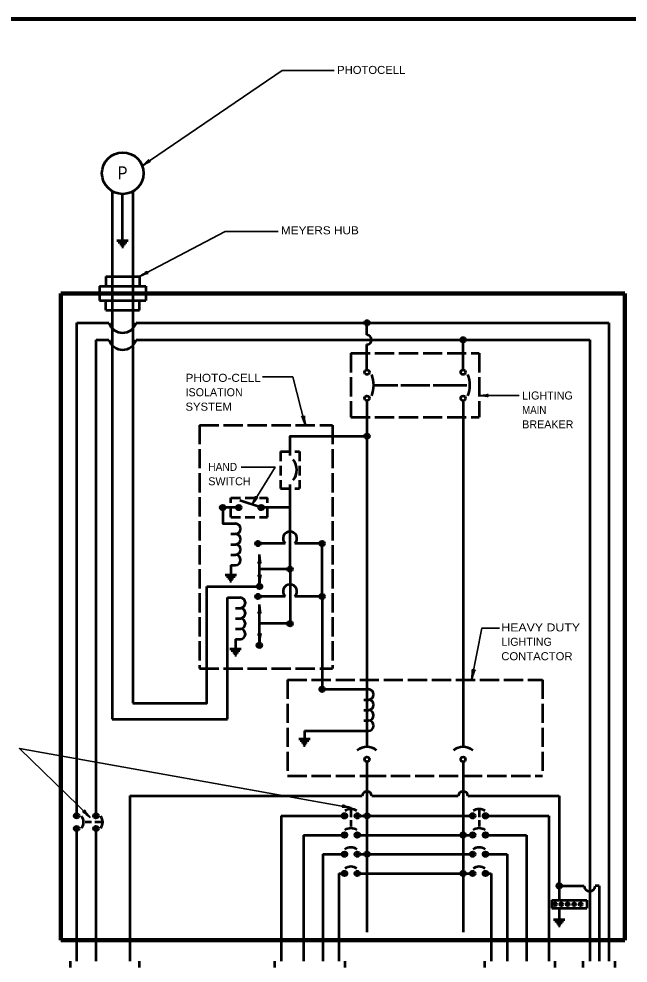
# Model space of a CAD drawing. Extents: x -35 to 821, y -18 to 526.
# Drawn here: x 359.2 to 587.3, y 165.4 to 519.2 of the extents above; entities that cross this region are included whole.
import ezdxf

# ---------------------------------------------------------------- set-up
doc = ezdxf.new("R2010")
doc.units = 0
doc.header["$LTSCALE"] = 1.2
doc.linetypes.add('LONG_DASHED', pattern=[7.5, 6, -1.5])
doc.linetypes.add('MEDIUM_DASHED', pattern=[4.5, 3, -1.5])
doc.layers.add('1', color=7, linetype='Continuous', lineweight=53)

msp = doc.modelspace()

# ---------------------------------------------------------------- hatches: boundary and pattern name
at = {"layer": '1'}
for points in [[(490.425, 405.327, 1), (488.625, 405.327, 1)], [(526.425, 398.986, 1), (524.625, 398.986, 1)], [(490.425, 362.807, 1), (488.625, 362.807, 1)], [(436.425, 336.107, 1), (434.625, 336.107, 1)], [(442.425, 336.107, 1), (440.625, 336.107, 1)], [(450.825, 336.107, 1), (449.025, 336.107, 1)], [(449.625, 322.607, 1), (447.825, 322.607, 1)], [(473.625, 322.607, 1), (471.825, 322.607, 1)], [(461.625, 313.007, 1), (459.825, 313.007, 1)], [(450.225, 306.557, 1), (448.425, 306.557, 1)], [(449.625, 302.807, 1), (447.825, 302.807, 1)], [(473.625, 302.807, 1), (471.825, 302.807, 1)], [(461.625, 292.607, 1), (459.825, 292.607, 1)], [(450.142, 284.482, 1), (448.342, 284.482, 1)], [(473.625, 268.007, 1), (471.825, 268.007, 1)], [(380.848, 219.726, 1), (380.848, 221.526, 1)], [(388.048, 219.726, 1), (388.048, 221.526, 1)], [(482.025, 220.607, 1), (480.225, 220.607, 1)], [(486.825, 220.607, 1), (485.025, 220.607, 1)], [(490.425, 220.607, 1), (488.625, 220.607, 1)], [(530.025, 220.607, 1), (528.225, 220.607, 1)], [(534.825, 220.607, 1), (533.025, 220.607, 1)], [(380.848, 214.926, 1), (380.848, 216.726, 1)], [(388.048, 214.926, 1), (388.048, 216.726, 1)], [(482.025, 213.407, 1), (480.225, 213.407, 1)], [(486.825, 213.407, 1), (485.025, 213.407, 1)], [(526.425, 213.407, 1), (524.625, 213.407, 1)], [(530.025, 213.407, 1), (528.225, 213.407, 1)], [(534.825, 213.407, 1), (533.025, 213.407, 1)], [(482.025, 206.207, 1), (480.225, 206.207, 1)], [(486.825, 206.207, 1), (485.025, 206.207, 1)], [(490.425, 206.207, 1), (488.625, 206.207, 1)], [(530.025, 206.207, 1), (528.225, 206.207, 1)], [(534.825, 206.207, 1), (533.025, 206.207, 1)], [(482.025, 199.007, 1), (480.225, 199.007, 1)], [(486.825, 199.007, 1), (485.025, 199.007, 1)], [(526.425, 199.007, 1), (524.625, 199.007, 1)], [(530.025, 199.007, 1), (528.225, 199.007, 1)], [(534.825, 199.007, 1), (533.025, 199.007, 1)], [(562.425, 194.357, 1), (560.625, 194.357, 1)], [(560.516, 187.457, 1), (559.316, 187.457, 1)], [(562.916, 187.457, 1), (561.716, 187.457, 1)], [(565.316, 187.457, 1), (564.116, 187.457, 1)], [(567.716, 187.457, 1), (566.516, 187.457, 1)], [(570.116, 187.457, 1), (568.916, 187.457, 1)]]:
    msp.add_hatch(color=256, dxfattribs=at).paths.add_polyline_path(points)

# ---------------------------------------------------------------- linework, layer by layer
for p, q in [((394.125, 454.661), (394.125, 256.757)), ((398.025, 436.177), (398.025, 453.577)), ((401.925, 454.583), (401.925, 262.757)), ((395.925, 436.177), (400.125, 436.177)), ((396.375, 435.577), (399.675, 435.577)), ((396.975, 434.977), (399.075, 434.977)), ((397.425, 434.377), (398.625, 434.377)), ((397.725, 433.777), (398.325, 433.777)), ((391.725, 422.657), (404.325, 422.657)), ((391.725, 422.657), (391.725, 419.057)), ((404.325, 422.657), (404.325, 419.057)), ((389.325, 419.057), (406.725, 419.057)), ((389.325, 419.057), (389.325, 413.657)), ((406.725, 419.057), (406.725, 413.657)), ((389.325, 413.657), (406.725, 413.657)), ((391.725, 410.057), (391.725, 413.657)), ((404.325, 410.057), (404.325, 413.657)), ((391.725, 410.057), (404.325, 410.057)), ((380.925, 405.327), (392.925, 405.327)), ((380.925, 220.607), (380.925, 405.327)), ((403.125, 405.327), (580.125, 405.327)), ((489.525, 400.786), (489.525, 405.327)), ((580.125, 405.327), (580.125, 166.157)), ((388.125, 398.986), (392.925, 398.986)), ((388.125, 220.607), (388.125, 398.986)), ((403.125, 398.986), (572.925, 398.986)), ((489.525, 387.707), (489.525, 397.186)), ((525.525, 387.707), (525.525, 398.986)), ((572.925, 398.986), (572.925, 166.157)), ((492.071, 381.932), (501.071, 381.932)), ((502.271, 381.932), (513.071, 381.932)), ((514.271, 381.932), (526.871, 381.932)), ((489.525, 376.157), (489.525, 246.407)), ((525.525, 376.157), (525.525, 246.407)), ((460.725, 313.007), (460.725, 344.807)), ((449.925, 336.107), (441.936, 338.703)), ((441.525, 336.107), (435.525, 336.107)), ((460.725, 336.107), (449.925, 336.107)), ((438.525, 326.207), (440.325, 326.207)), ((438.525, 322.307), (440.325, 322.307)), ((458.925, 322.607), (448.725, 322.607)), ((449.325, 307.457), (449.325, 318.557)), ((438.525, 318.407), (440.325, 318.407)), ((438.525, 314.507), (440.325, 314.507)), ((438.525, 314.507), (438.525, 310.907)), ((460.725, 313.007), (449.325, 313.007)), ((436.425, 310.907), (440.625, 310.907)), ((436.875, 310.307), (440.175, 310.307)), ((437.475, 309.707), (439.575, 309.707)), ((437.925, 309.107), (439.125, 309.107)), ((438.225, 308.507), (438.825, 308.507)), ((429.525, 306.557), (449.325, 306.557)), ((437.325, 256.757), (437.325, 302.357)), ((437.325, 302.357), (442.125, 302.357)), ((458.925, 302.807), (448.725, 302.807)), ((472.725, 302.807), (462.525, 302.807)), ((440.325, 298.457), (442.125, 298.457)), ((449.325, 285.407), (449.325, 299.807)), ((440.325, 294.557), (442.125, 294.557)), ((440.325, 290.657), (442.125, 290.657)), ((440.325, 286.757), (442.125, 286.757)), ((440.325, 286.757), (440.325, 283.157)), ((438.225, 283.157), (442.425, 283.157)), ((438.675, 282.557), (441.975, 282.557)), ((439.275, 281.957), (441.375, 281.957)), ((439.725, 281.357), (440.925, 281.357)), ((440.025, 280.757), (440.625, 280.757)), ((489.525, 268.007), (490.125, 268.007)), ((488.325, 264.107), (490.125, 264.107)), ((488.325, 260.207), (490.125, 260.207)), ((394.125, 256.757), (437.325, 256.757)), ((488.325, 256.307), (490.125, 256.307)), ((466.125, 252.407), (490.125, 252.407)), ((466.125, 252.407), (466.125, 249.407)), ((464.025, 249.407), (468.225, 249.407)), ((464.475, 248.807), (467.775, 248.807)), ((465.075, 248.207), (467.175, 248.207)), ((465.525, 247.607), (466.725, 247.607)), ((465.825, 247.007), (466.425, 247.007)), ((489.525, 240.857), (489.525, 176.957)), ((525.525, 240.857), (525.525, 176.957)), ((400.725, 228.107), (400.725, 166.157)), ((400.725, 228.107), (487.725, 228.107)), ((491.325, 228.107), (523.725, 228.107)), ((527.325, 228.107), (561.525, 228.107)), ((561.525, 228.107), (561.525, 188.957)), ((388.125, 219.694), (388.125, 220.607)), ((457.425, 220.607), (457.425, 166.157)), ((457.425, 220.607), (481.125, 220.607)), ((483.525, 222.551), (483.525, 220.151)), ((485.925, 220.607), (529.125, 220.607)), ((531.525, 222.551), (531.525, 220.151)), ((533.925, 220.607), (557.625, 220.607)), ((557.625, 220.607), (557.625, 166.157)), ((386.391, 218.226), (383.991, 218.226)), ((389.991, 218.226), (387.591, 218.226)), ((388.125, 166.157), (388.125, 215.847)), ((483.525, 218.951), (483.525, 216.551)), ((531.525, 218.951), (531.525, 216.551)), ((380.925, 166.157), (380.925, 215.731)), ((465.825, 213.407), (481.125, 213.407)), ((465.825, 213.407), (465.825, 166.157)), ((485.925, 213.407), (529.125, 213.407)), ((533.925, 213.407), (549.225, 213.407)), ((549.225, 213.407), (549.225, 166.157)), ((473.025, 206.207), (481.125, 206.207)), ((473.025, 206.207), (473.025, 166.157)), ((485.925, 206.207), (529.125, 206.207)), ((533.925, 206.207), (542.025, 206.207)), ((542.025, 206.207), (542.025, 166.157)), ((479.025, 199.007), (481.125, 199.007)), ((479.025, 199.007), (479.025, 166.157)), ((485.925, 199.007), (529.125, 199.007)), ((533.925, 199.007), (536.025, 199.007)), ((536.025, 199.007), (536.025, 166.157)), ((561.525, 194.357), (570.825, 194.357)), ((576.525, 194.357), (575.025, 194.357)), ((576.525, 194.357), (576.525, 166.157)), ((558.716, 188.957), (571.916, 188.957)), ((558.716, 188.957), (558.716, 185.957)), ((571.916, 188.957), (571.916, 185.957)), ((558.716, 185.957), (571.916, 185.957)), ((561.525, 185.957), (561.525, 181.757)), ((559.425, 181.757), (563.625, 181.757)), ((559.875, 181.157), (563.175, 181.157)), ((560.475, 180.557), (562.575, 180.557)), ((560.925, 179.957), (562.125, 179.957)), ((561.225, 179.357), (561.825, 179.357)), ((378.525, 163.757), (378.525, 166.157)), ((404.325, 163.757), (404.325, 166.157)), ((455.025, 163.757), (455.025, 166.157)), ((481.425, 163.757), (481.425, 166.157)), ((533.625, 163.757), (533.625, 166.157)), ((560.025, 163.757), (560.025, 166.157)), ((570.525, 163.757), (570.525, 166.157)), ((582.525, 163.757), (582.525, 166.157))]:
    msp.add_line(p, q, dxfattribs=at)
at = {"layer": '1', "lineweight": 140}
for p, q in [((374.925, 416.357), (374.925, 173.957)), ((374.925, 416.357), (586.125, 416.357)), ((586.125, 416.357), (586.125, 173.957)), ((374.925, 173.957), (586.125, 173.957))]:
    msp.add_line(p, q, dxfattribs=at)
at = {"layer": '1', "linetype": 'LONG_DASHED'}
for p, q in [((483.525, 393.932), (531.525, 393.932)), ((483.525, 393.932), (483.525, 369.932)), ((531.525, 393.932), (531.525, 369.932)), ((483.525, 369.932), (531.525, 369.932)), ((426.825, 367.007), (476.625, 367.007)), ((426.825, 367.007), (426.825, 275.807)), ((476.625, 367.007), (476.625, 275.807)), ((426.825, 275.807), (476.625, 275.807)), ((459.825, 271.607), (555.225, 271.607)), ((459.825, 271.607), (459.825, 235.607)), ((555.225, 271.607), (555.225, 235.607))]:
    msp.add_line(p, q, dxfattribs=at)
at = {"layer": '1', "lineweight": 35}
msp.add_line((531.525, 378.087), (546.475, 378.087), dxfattribs=at)
at = {"layer": '1', "linetype": 'MEDIUM_DASHED'}
for p, q in [((457.125, 357.107), (464.325, 357.107)), ((457.125, 357.107), (457.125, 343.307)), ((464.325, 357.107), (464.325, 343.307)), ((457.125, 343.307), (464.325, 343.307)), ((438.525, 332.507), (438.525, 339.707)), ((438.525, 339.707), (452.325, 339.707)), ((452.325, 332.507), (452.325, 339.707)), ((438.525, 332.507), (452.325, 332.507))]:
    msp.add_line(p, q, dxfattribs=at)
at = {"layer": '1', "lineweight": 158}
msp.add_lwpolyline([(814.433, 519.216), (22.733, 519.116), (22.833, -6.884)], dxfattribs=at)
at = {"layer": '1', "lineweight": 35}
for points in [[(405.37, 464.185), (457.828, 499.822), (477.268, 499.822)], [(404.325, 422.657), (436.444, 439.538), (456.273, 439.538)], [(466.431, 367.007), (461.716, 385.088), (450.441, 385.088)], [(446.529, 337.211), (455.106, 351.251), (442.413, 351.251)], [(528.794, 271.953), (532.587, 290.924), (539.197, 290.924)], [(483.603, 223.645), (359.39, 245.857), (385.834, 220.031)]]:
    msp.add_lwpolyline(points, dxfattribs=at)
at = {"layer": '1'}
for points in [[(460.725, 355.607), (460.725, 362.807), (489.525, 362.807)], [(435.525, 336.107), (435.525, 330.107), (440.325, 330.107)], [(472.725, 302.807), (472.725, 322.607), (462.525, 322.607)], [(460.725, 313.007), (460.725, 292.607), (449.325, 292.607)], [(401.925, 262.757), (429.525, 262.757), (429.525, 306.557)], [(472.725, 302.807), (472.725, 268.007), (489.525, 268.007)]]:
    msp.add_lwpolyline(points, dxfattribs=at)
at = {"layer": '1', "linetype": 'LONG_DASHED'}
msp.add_lwpolyline([(459.825, 235.607), (489.525, 235.607), (525.525, 235.607), (555.225, 235.607)], dxfattribs=at)
at = {"layer": '1'}
for centre, radius in [((398.093, 461.377), 7.8), ((489.525, 405.327), 0.9), ((525.525, 398.986), 0.9), ((489.525, 386.807), 0.9), ((525.525, 386.807), 0.9), ((489.525, 377.057), 0.9), ((525.525, 377.057), 0.9), ((489.525, 362.807), 0.9), ((435.525, 336.107), 0.9), ((441.525, 336.107), 0.9), ((449.925, 336.107), 0.9), ((448.725, 322.607), 0.9), ((472.725, 322.607), 0.9), ((460.725, 313.007), 0.9), ((449.325, 306.557), 0.9), ((448.725, 302.807), 0.9), ((472.725, 302.807), 0.9), ((460.725, 292.607), 0.9), ((449.242, 284.482), 0.9), ((472.725, 268.007), 0.9), ((489.525, 241.757), 0.9), ((525.525, 241.757), 0.9), ((380.848, 220.626), 0.9), ((388.048, 220.626), 0.9), ((481.125, 220.607), 0.9), ((485.925, 220.607), 0.9), ((489.525, 220.607), 0.9), ((529.125, 220.607), 0.9), ((533.925, 220.607), 0.9), ((380.848, 215.826), 0.9), ((388.048, 215.826), 0.9), ((481.125, 213.407), 0.9), ((485.925, 213.407), 0.9), ((525.525, 213.407), 0.9), ((529.125, 213.407), 0.9), ((533.925, 213.407), 0.9), ((481.125, 206.207), 0.9), ((485.925, 206.207), 0.9), ((489.525, 206.207), 0.9), ((529.125, 206.207), 0.9), ((533.925, 206.207), 0.9), ((481.125, 199.007), 0.9), ((485.925, 199.007), 0.9), ((525.525, 199.007), 0.9), ((529.125, 199.007), 0.9), ((533.925, 199.007), 0.9), ((561.525, 194.357), 0.9), ((559.916, 187.457), 0.6), ((562.316, 187.457), 0.6), ((564.716, 187.457), 0.6), ((567.116, 187.457), 0.6), ((569.516, 187.457), 0.6)]:
    msp.add_circle(centre, radius, dxfattribs=at)
for centre, radius, start, end in [((398.025, 406.911), 5.34, 197.26122, 342.73878), ((489.377, 398.985), 1.806, 274.71933, 85.28067), ((398.025, 400.57), 5.34, 197.26122, 342.73878), ((481.107, 381.932), 10.964, 338.74274, 21.25726), ((517.107, 381.932), 10.964, 338.74274, 21.25726), ((456.722, 350.207), 6.503, 323.14889, 36.85111), ((440.242, 328.157), 1.952, 272.45324, 87.54675), ((440.242, 324.257), 1.952, 272.45324, 87.54675), ((460.725, 324.49), 2.604, 313.71808, 226.28192), ((440.242, 320.357), 1.952, 272.45324, 87.54675), ((440.242, 316.457), 1.952, 272.45324, 87.54675), ((460.725, 304.69), 2.604, 313.71808, 226.28192), ((442.042, 300.407), 1.952, 272.45324, 87.54675), ((442.042, 296.507), 1.952, 272.45324, 87.54675), ((442.042, 292.607), 1.952, 272.45324, 87.54675), ((442.042, 288.707), 1.952, 272.45324, 87.54675), ((490.042, 266.057), 1.952, 272.45324, 87.54675), ((490.042, 262.157), 1.952, 272.45324, 87.54675), ((490.042, 258.257), 1.952, 272.45324, 87.54675), ((490.042, 254.357), 1.952, 272.45324, 87.54675), ((489.525, 240.932), 5.475, 48.88791, 131.11209), ((525.525, 240.932), 5.475, 48.88791, 131.11209), ((489.525, 227.959), 1.806, 4.71933, 175.28067), ((525.525, 227.959), 1.806, 4.71933, 175.28067), ((483.525, 219.376), 3.775, 53.41416, 126.58584), ((531.525, 219.376), 3.775, 53.41416, 126.58584), ((379.616, 218.226), 3.775, 323.41416, 36.58584), ((386.816, 218.226), 3.775, 323.41416, 36.58584), ((483.525, 212.176), 3.775, 53.41416, 126.58584), ((531.525, 212.176), 3.775, 53.41416, 126.58584), ((483.525, 204.976), 3.775, 53.41416, 126.58584), ((531.525, 204.976), 3.775, 53.41416, 126.58584), ((483.525, 197.776), 3.775, 53.41416, 126.58584), ((531.525, 197.776), 3.775, 53.41416, 126.58584), ((572.925, 194.38), 2.1, 180.62582, 359.37418)]:
    msp.add_arc(centre, radius, start, end, dxfattribs=at)
at = {"layer": '1', "lineweight": 40}
for centre, major_axis, ratio, start_param, end_param in [((406.266, 465.195), (-1.667, -1.359), 0.122415, 0.8963533, 3.1415927), ((406.625, 464.731), (1.862, 1.01), 0.07063, 6.2823074, 8.5597026), ((405.33, 423.56), (-1.81, -1.163), 0.122415, 0.8963533, 3.1415927), ((405.33, 423.56), (-1.81, -1.163), 0.122415, 0.8963533, 3.1415927), ((405.634, 423.058), (-1.964, -0.794), 0.07063, 3.1407148, 5.41811), ((405.634, 423.058), (-1.964, -0.794), 0.07063, 3.1407148, 5.41811), ((532.835, 378.418), (-2.143, -0.187), 0.122415, 0.8963533, 3.1415927), ((532.835, 378.418), (-2.143, -0.187), 0.122415, 0.8963533, 3.1415927), ((532.87, 377.833), (-2.108, 0.211), 0.07063, 3.1407148, 5.41811), ((532.87, 377.833), (-2.108, 0.211), 0.07063, 3.1407148, 5.41811), ((465.78, 368.191), (0.722, -2.026), 0.122415, 0.8963533, 3.1415927), ((465.78, 368.191), (0.722, -2.026), 0.122415, 0.8963533, 3.1415927), ((466.338, 368.373), (0.328, -2.093), 0.07063, 3.1407148, 5.41811), ((466.338, 368.373), (0.328, -2.093), 0.07063, 3.1407148, 5.41811), ((446.929, 338.501), (-0.957, -1.926), 0.122415, 0.8963533, 3.1415927), ((446.929, 338.501), (-0.957, -1.926), 0.122415, 0.8963533, 3.1415927), ((447.447, 338.226), (1.279, 1.689), 0.07063, 6.2823074, 8.5597026), ((447.447, 338.226), (1.279, 1.689), 0.07063, 6.2823074, 8.5597026), ((449.071, 317.213), (0.211, 2.108), 0.07063, 3.1407148, 5.41811), ((449.657, 317.248), (-0.187, 2.143), 0.122415, 0.8963533, 3.1415927), ((448.994, 308.767), (0.187, -2.143), 0.122415, 0.8963533, 3.1415927), ((449.579, 308.802), (-0.211, -2.108), 0.07063, 3.1407148, 5.41811), ((449.071, 298.463), (0.211, 2.108), 0.07063, 3.1407148, 5.41811), ((449.657, 298.498), (-0.187, 2.143), 0.122415, 0.8963533, 3.1415927), ((448.994, 286.717), (0.187, -2.143), 0.122415, 0.8963533, 3.1415927), ((449.579, 286.752), (-0.211, -2.108), 0.07063, 3.1407148, 5.41811), ((528.726, 273.302), (-0.236, -2.138), 0.122415, 0.8963533, 3.1415927), ((529.307, 273.222), (0.62, 2.026), 0.07063, 6.2823074, 8.5597026), ((482.255, 223.549), (2.142, -0.193), 0.122415, 0.8963533, 3.1415927), ((482.324, 224.131), (-2.038, 0.579), 0.07063, 6.2823074, 8.5597026), ((384.665, 220.708), (1.664, -1.363), 0.122415, 0.8963533, 3.1415927), ((385.049, 221.152), (-1.361, 1.624), 0.07063, 6.2823074, 8.5597026)]:
    msp.add_ellipse(centre, major_axis=major_axis, ratio=ratio, start_param=start_param, end_param=end_param, dxfattribs=at)

# ---------------------------------------------------------------- texts
at = {"layer": '1'}
for s, height, width, p in [('PHOTOCELL', 3, 1.05, (478.361, 498.589)), ('P', 4.8, 0.85, (396.203, 459.13)), ('MEYERS HUB', 3, 1.1, (457.312, 438.498)), ('PHOTO-CELL', 3, 1.1, (421.6, 383.214)), ('SYSTEM', 3, 1.05, (421.6, 372.414)), ('MAIN', 3, 0.9, (547.656, 371.19)), ('HAND', 3, 0.95, (430.115, 349.856)), ('HEAVY DUTY', 3, 1.15, (539.834, 289.699)), ('CONTACTOR', 3, 1.05, (539.834, 278.899))]:
    msp.add_text(s, height=height, dxfattribs=dict(at, width=width)).set_placement(p)
for s, p in [('ISOLATION', (421.6, 377.814)), ('LIGHTING', (547.656, 376.59)), ('BREAKER', (547.656, 365.79)), ('SWITCH', (430.115, 344.456)), ('LIGHTING', (539.834, 284.299))]:
    msp.add_text(s, height=3, dxfattribs=at).set_placement(p)

doc.saveas('drawing.dxf')
